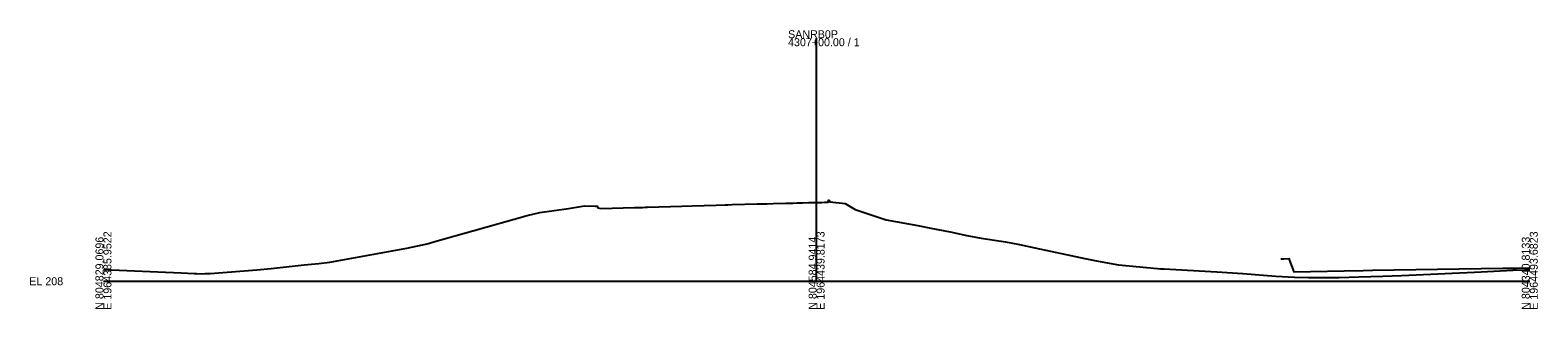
# Model space of a CAD drawing. Extents: x 1995641 to 1997170, y 790368 to 809963.
# Drawn here: x 1996641 to 1997170, y 797868 to 797966 of the extents above; entities that cross this region are included whole.
import ezdxf

# ---------------------------------------------------------------- set-up
doc = ezdxf.new("R2010")
doc.units = 0
for name, color, linetype in [('Default', 7, 'Continuous'), ('RD_GPK_XS_Cell', 7, 'Continuous'), ('RD_Sketch1', 7, 'Continuous'), ('RD_XS_ExGround', 7, 'Continuous'), ('RD_XS_Pave', 7, 'Continuous')]:
    doc.layers.add(name, color=color, linetype=linetype)

msp = doc.modelspace()

# ---------------------------------------------------------------- linework, layer by layer
at = {"layer": 'RD_GPK_XS_Cell'}
for p, q in [((1996917.06, 797878.11), (1996917.06, 797963.35)), ((1996667.06, 797878.11), (1996917.06, 797878.11)), ((1996917.06, 797878.11), (1997167.06, 797878.11))]:
    msp.add_line(p, q, dxfattribs=at)
at = {"layer": 'RD_XS_ExGround'}
msp.add_lwpolyline([(1996667.06, 797882.24), (1996694.26, 797881.04), (1996698.84, 797880.8), (1996699.62, 797880.77), (1996701.42, 797880.76), (1996702.68, 797880.8), (1996704.5, 797880.86), (1996720.88, 797882.09), (1996725.85, 797882.61), (1996737.44, 797883.9), (1996742.52, 797884.34), (1996746.43, 797884.81), (1996773.41, 797889.67), (1996780.49, 797891.26), (1996784.07, 797892.25), (1996796.53, 797895.77), (1996815.54, 797901.15), (1996820.01, 797902.2), (1996830.08, 797903.59), (1996835.73, 797904.55), (1996839.44, 797904.47), (1996840.26, 797904.48), (1996840.36, 797903.84), (1996841.46, 797903.6), (1996853.2, 797903.97), (1996856.02, 797904.03), (1996857.01, 797904.07), (1996857.76, 797904.09), (1996869.78, 797904.47), (1996873.39, 797904.57), (1996881.85, 797904.83), (1996884.99, 797904.93), (1996885.94, 797904.95), (1996887.49, 797905), (1996896.19, 797905.24), (1996899.57, 797905.31), (1996901.82, 797905.35), (1996906.17, 797905.47), (1996907.39, 797905.5), (1996908.74, 797905.53), (1996910.18, 797905.56), (1996912.07, 797905.61), (1996914.18, 797905.68), (1996917.06, 797905.74), (1996918.95, 797905.78), (1996919.78, 797905.8), (1996921.11, 797905.82), (1996921.21, 797906.52), (1996921.36, 797906.53), (1996921.65, 797905.91), (1996927.03, 797905.42), (1996930.54, 797903.28), (1996941.45, 797899.62), (1996952.51, 797897.72), (1996957.16, 797896.74), (1996963.88, 797895.48), (1996969.69, 797894.1), (1996974.7, 797893.23), (1996983.26, 797891.89), (1996988.2, 797891.02), (1996993.56, 797889.86), (1997004.53, 797887.53), (1997011.09, 797886.12), (1997015.76, 797885.2), (1997022.92, 797883.91), (1997036.58, 797882.59), (1997037.65, 797882.48), (1997038.07, 797882.46), (1997038.88, 797882.43), (1997057.4, 797881.44), (1997066.43, 797880.78), (1997078.06, 797879.93), (1997084.54, 797879.59), (1997089.47, 797879.39), (1997090.94, 797879.41), (1997100.19, 797879.38), (1997107.16, 797879.63), (1997115.56, 797879.87), (1997122.14, 797880.16), (1997132.37, 797880.56), (1997139.87, 797880.99), (1997147.74, 797881.33), (1997150.02, 797881.46), (1997161.15, 797882.04), (1997165.18, 797882.13), (1997167.06, 797882.16)], dxfattribs=at)
at = {"layer": 'RD_XS_Pave'}
msp.add_lwpolyline([(1997079.78, 797886.02), (1997080.87, 797886.02), (1997082.65, 797886.03), (1997083.24, 797884.45), (1997084.38, 797881.37), (1997090.24, 797881.49), (1997102.04, 797881.75), (1997108.67, 797881.89), (1997111.97, 797881.96), (1997134.69, 797882.3), (1997157.57, 797882.64), (1997162.37, 797882.71), (1997167.06, 797882.78)], dxfattribs=at)

# ---------------------------------------------------------------- texts
at = {"layer": 'Default'}
msp.add_text('-', height=0.0001, dxfattribs=at).set_placement((1996667.06, 797878.11))
msp.add_text('-', height=0.0001, dxfattribs=at).set_placement((1996667.06, 797878.11))
at = {"layer": 'RD_GPK_XS_Cell'}
for s, p in [('4307+00.00 / 1', (1996907.06, 797960.55)), ('SANRB0P', (1996907.06, 797963.35)), ('EL 208', (1996641.06, 797876.71))]:
    msp.add_text(s, height=2.8, dxfattribs=at).set_placement(p)
for s, p in [('E 1964385.9522', (1996669.86, 797868.11)), ('E 1964439.8173', (1996919.86, 797868.11)), ('E 1964493.6823', (1997169.86, 797868.11)), ('N 804829.0696', (1996667.06, 797868.11)), ('N 804584.9414', (1996917.06, 797868.11)), ('N 804340.8133', (1997167.06, 797868.11))]:
    msp.add_text(s, height=2.8, rotation=90, dxfattribs=at).set_placement(p)
at = {"layer": 'RD_Sketch1'}
msp.add_text('235.62', height=0.1, dxfattribs=at).set_placement((1996916.85, 797905.64))

doc.saveas('drawing.dxf')
